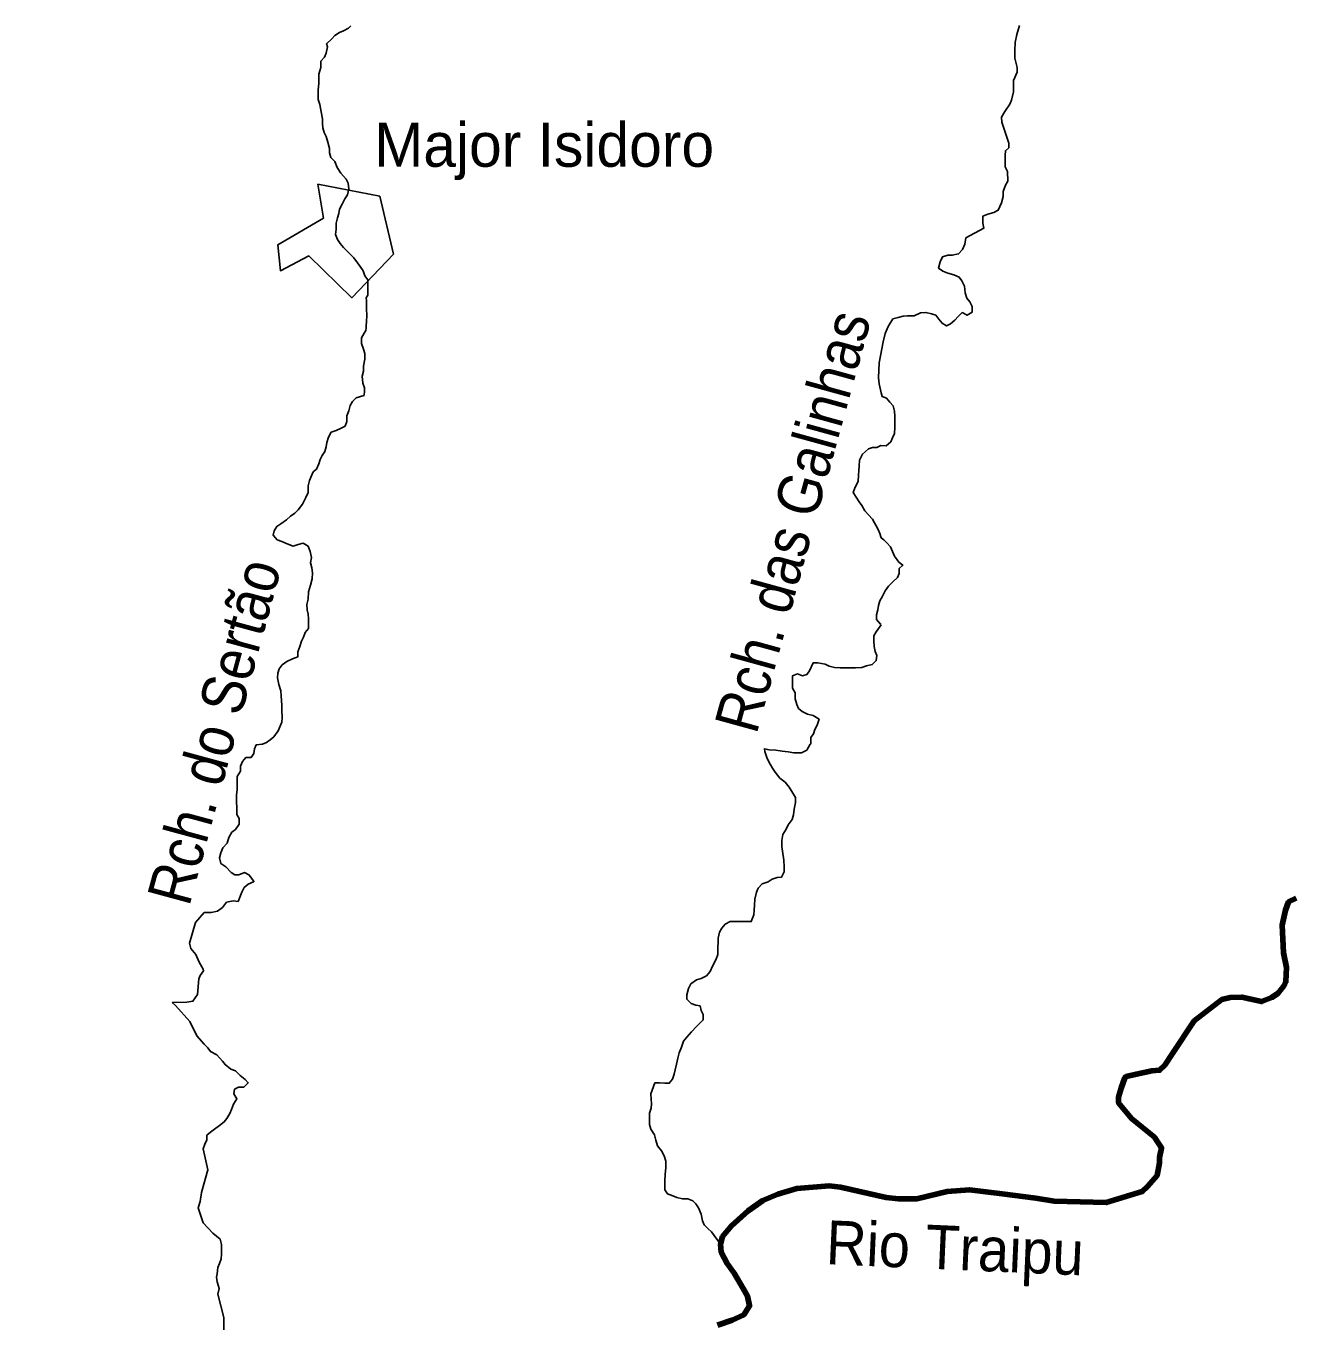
# Model space of a CAD drawing. Extents: x -1643653 to 4543381, y 1624270 to 13878484.
# Drawn here: x 717468 to 731879, y 8933563 to 8948296 of the extents above; entities that cross this region are included whole.
import ezdxf
from ezdxf.enums import TextEntityAlignment as Align

# ---------------------------------------------------------------- set-up
doc = ezdxf.new("R2010")
doc.units = 0
doc.header["$LTSCALE"] = 160
for name, color, linetype, lineweight in [('21', 7, 'Continuous', 25), ('24', 7, 'Continuous', 25), ('53', 7, 'Continuous', 106), ('60', 7, 'Continuous', 13)]:
    doc.layers.add(name, color=color, linetype=linetype, lineweight=lineweight)
doc.layers.add('41', color=7, linetype='Continuous')
doc.layers.add('49', color=7, linetype='Continuous')

msp = doc.modelspace()

# ---------------------------------------------------------------- linework, layer by layer
at = {"layer": '21'}
msp.add_lwpolyline([(720787.1, 8946496.4), (720850.6, 8946110.2), (720334.5, 8945806.5), (720363, 8945511.1), (720684.9, 8945680.2), (721175.9, 8945203.6), (721647.6, 8945700.8), (721491.5, 8946358.8)], close=True, dxfattribs=at)
at = {"layer": '24'}
for points in [[(721162.8, 8948295.4), (721135.4, 8948272.2), (721079.2, 8948242), (721033.3, 8948221.9), (720982.2, 8948186.6), (720946.4, 8948151.1), (720887.8, 8948093.3)], [(728769.3, 8948300.4), (728738.1, 8948198.8), (728717.1, 8948107.2), (728716.5, 8948015.6), (728715.9, 8947929), (728740.6, 8947821.9), (728740.2, 8947771), (728698.8, 8947674.5), (728698.3, 8947603.2), (728698, 8947547.2), (728677, 8947450.6), (728656.3, 8947404.9), (728599.8, 8947323.7), (728563.7, 8947257.7), (728568.4, 8947201.7), (728648.1, 8946961.9), (728647.8, 8946910.9), (728606.8, 8946875.6), (728606.5, 8946824.6), (728605.9, 8946743.2), (728605.6, 8946692.2), (728630.7, 8946641.2), (728635, 8946529.1), (728609.2, 8946483.4), (728583.3, 8946412.3), (728582.9, 8946356.3), (728562.1, 8946285.1), (728525.9, 8946198.8), (728474.8, 8946173.6), (728408.6, 8946153.6), (728352.5, 8946133.6), (728351.9, 8946052.1), (728361.7, 8945996.1), (728366, 8945992.5)], [(720886.8, 8948096.7), (720898.2, 8948057.6), (720882.5, 8947986.4), (720861.8, 8947940.7), (720820.8, 8947895.1), (720820.3, 8947823.8), (720799.5, 8947747.6), (720798.7, 8947640.7), (720793.1, 8947569.4), (720792.8, 8947518.5), (720792.4, 8947457.4), (720812.3, 8947401.2), (720827, 8947319.7), (720841.7, 8947238.1), (720841.4, 8947187.2), (720846.1, 8947136.2), (720861, 8947085.2), (720881, 8947039.2), (720900.9, 8946972.9), (720920.8, 8946901.5), (720920.4, 8946850.6), (720935.3, 8946799.6), (720980.8, 8946753.5), (721005.7, 8946687.1), (721051.1, 8946620.6), (721111.6, 8946554.1), (721131.6, 8946508.1), (721141.3, 8946441.8), (721125.6, 8946375.7), (721094.8, 8946330.1), (721063.9, 8946269.2), (721033, 8946213.3), (721027.5, 8946162.4), (721011.9, 8946111.6), (720996.2, 8946050.6), (720995.8, 8945984.4), (720990.3, 8945923.3), (721010.2, 8945867.2), (721040.4, 8945821.2), (721080.8, 8945775.1), (721116.2, 8945739.2), (721156.6, 8945698.2), (721197, 8945657.3), (721237.2, 8945601), (721267.5, 8945560.1)], [(728361.7, 8945996.1), (728157.5, 8945885.3), (728146.8, 8945814.1), (728121, 8945753.1), (728074.9, 8945702.5), (728003.6, 8945687.6), (727952.7, 8945687.9), (727891.5, 8945667.9), (727865.7, 8945612.1), (727844.9, 8945540.9), (727895.5, 8945505), (727951.3, 8945484.2), (728022.4, 8945463.4), (728083.2, 8945437.6), (728113.5, 8945396.7), (728143.5, 8945335.4), (728148.1, 8945259), (728168, 8945197.7), (728203.3, 8945156.8), (728228.4, 8945105.7), (728228, 8945039.5), (728171.8, 8945004.2), (728116, 8945035.1), (728069.9, 8944989.6), (728034.1, 8944949), (727982.9, 8944908.6), (727937, 8944883.4), (727886.3, 8944914.3), (727851, 8944960.3), (727815.8, 8945006.4), (727765, 8945022), (727704.1, 8945037.6), (727643, 8945032.9), (727571.6, 8944997.7), (727495.3, 8944998.2), (727444.4, 8944993.4), (727388.3, 8944978.4), (727327.2, 8944963.6), (727273, 8944875.7), (727239.5, 8944797.4), (727239.5, 8944797.4), (727217.1, 8944704.3), (727172.4, 8944462.1)], [(721267.5, 8945560.1), (721302.7, 8945508.9), (721322.7, 8945452.8), (721358, 8945406.8), (721357.6, 8945345.6), (721357.2, 8945289.6), (721356.8, 8945233.6), (721336.6, 8945202.4)], [(721333.1, 8944831.8), (721314, 8944802.2), (721283.1, 8944746.3), (721282.7, 8944685.2), (721307.7, 8944618.9), (721322.6, 8944567.9), (721322.1, 8944506.8), (721306.3, 8944425.4), (721305.9, 8944369.4), (721290.3, 8944313.4), (721299.9, 8944231.9), (721319.9, 8944180.8), (721319.5, 8944129.9), (721309.9, 8944083.2)], [(727172.4, 8944462.1), (727164.9, 8944294.4), (727172.4, 8944223.6), (727194.7, 8944123), (727205.5, 8944081.4), (727256.2, 8944060.7), (727291.5, 8944014.6), (727331.9, 8943973.7), (727346.8, 8943912.4), (727351.5, 8943856.4), (727351.1, 8943800.4), (727350.6, 8943729.1), (727345, 8943657.8), (727324.3, 8943612.1), (727303.7, 8943566.4), (727252.5, 8943520.9), (727191.5, 8943521.3), (727145.6, 8943501.2), (727094.7, 8943501.5), (727048.8, 8943486.5), (726982.3, 8943425.8), (726946.2, 8943354.7), (726945.7, 8943288.5), (726940.3, 8943237.7), (726934.9, 8943186.8), (726934.4, 8943115.5), (726898.3, 8943049.5), (726877.6, 8942988.5), (726942.9, 8942881.2), (726973.2, 8942840.2), (727008.3, 8942778.9), (727094.2, 8942686.7), (727159.5, 8942569.2), (727179.5, 8942523.2), (727194.4, 8942472.2)], [(721311.4, 8944090.8), (721222.4, 8944064.3), (721181.5, 8944023.8), (721155.7, 8943978.2), (721140.1, 8943917.2), (721119.3, 8943861.3), (721118.9, 8943795.1), (721098.2, 8943744.3), (721052.2, 8943719.1), (720996.1, 8943694), (720940, 8943673.9), (720909.1, 8943618.1), (720888.3, 8943557.1), (720882.9, 8943506.2), (720867.3, 8943455.4), (720836.5, 8943409.8), (720815.8, 8943364.1), (720800.2, 8943313.2), (720774.3, 8943252.3), (720733.5, 8943222), (720712.8, 8943171.2), (720692.1, 8943125.5), (720676.4, 8943064.5), (720675.9, 8942988.1), (720650.1, 8942932.2), (720613.9, 8942856.1), (720562.6, 8942790.2), (720526.8, 8942754.7), (720475.7, 8942719.4), (720429.6, 8942678.9), (720368.3, 8942633.5), (720322.3, 8942603.2), (720291.4, 8942552.5), (720280.9, 8942501.6), (720326.3, 8942450.4), (720377, 8942429.8), (720437.9, 8942403.9), (720508.9, 8942378), (720565, 8942398), (720621, 8942413), (720676.7, 8942377), (720701.7, 8942315.7), (720716.5, 8942249.4), (720706, 8942188.4), (720720.8, 8942132.3), (720725.5, 8942076.2), (720725, 8942004.9), (720704.2, 8941933.8), (720683.3, 8941857.5), (720677.7, 8941776.1), (720662, 8941715.1), (720666.7, 8941653.9), (720676.5, 8941602.9), (720681.2, 8941552), (720680.8, 8941501.1), (720680.4, 8941440), (720644.5, 8941394.3), (720623.8, 8941343.6), (720603.2, 8941297.8), (720582.4, 8941236.9), (720561.6, 8941175.9), (720561.2, 8941119.9), (720500, 8941094.8), (720433.7, 8941064.6), (720382.6, 8941029.3), (720346.7, 8940983.7), (720331.1, 8940932.9), (720330.7, 8940881.9), (720345.5, 8940805.5), (720365.3, 8940734), (720370, 8940672.9), (720374.7, 8940621.9), (720379.4, 8940565.9), (720379, 8940509.9), (720383.5, 8940428.4), (720378.1, 8940377.5), (720336.7, 8940275.9), (720285.4, 8940210), (720244.5, 8940174.6), (720203.6, 8940144.3), (720157.6, 8940124.2), (720086.4, 8940119.6), (720065.7, 8940073.9), (720060.3, 8940017.9), (720029.4, 8939972.2), (719968.4, 8939972.6), (719932.5, 8939927), (719906.7, 8939876.2), (719906.3, 8939820.2), (719870.3, 8939759.3), (719869.9, 8939703.3), (719869.3, 8939611.7), (719863.7, 8939545.5), (719863.2, 8939464), (719867.9, 8939408), (719867.3, 8939326.5), (719892.4, 8939280.5), (719892, 8939214.3), (719850.8, 8939153.5), (719810, 8939123.2), (719773.9, 8939062.3)], [(727194.4, 8942472.2), (727224.8, 8942451.7), (727260.1, 8942415.8), (727300.5, 8942369.7), (727345.5, 8942262.5), (727395.9, 8942196), (727441.4, 8942160.1), (727443.2, 8942160.1)], [(727441.4, 8942160.1), (727400.5, 8942124.7), (727400.1, 8942068.7), (727379.5, 8942023), (727328.2, 8941972.3), (727277, 8941921.7), (727241.1, 8941871), (727205, 8941800), (727179.2, 8941754.3), (727163.6, 8941703.5), (727158.2, 8941652.6), (727142.6, 8941596.7), (727142.2, 8941545.7), (727187.6, 8941489.4), (727193.7, 8941485.1)], [(727194.1, 8941484.8), (727136.1, 8941403.2), (727110.4, 8941357.5), (727110, 8941301.5), (727114.6, 8941235.3), (727124.4, 8941179.2), (727144.4, 8941133.2), (727139, 8941077.2), (727092.9, 8941031.7), (727026.7, 8941016.8), (726975.7, 8940996.8), (726904.4, 8940992.1), (726853.6, 8940992.4), (726792.5, 8940992.8), (726726.4, 8940993.2), (726665.4, 8940998.7), (726604.5, 8941014.3), (726558.9, 8941035), (726472.5, 8941050.8), (726421.7, 8941051.1), (726380.3, 8940959.7), (726349.5, 8940919.1), (726298.6, 8940904.2), (726242.8, 8940924.9), (726186.7, 8940904.8), (726186.2, 8940833.6), (726185.7, 8940762.3), (726215.9, 8940711.2), (726215.4, 8940639.9), (726235.3, 8940578.6), (726255.3, 8940532.7), (726295.8, 8940496.8), (726356.6, 8940465.9), (726422.6, 8940450.2), (726488.4, 8940409), (726467.6, 8940343), (726441.8, 8940292.2), (726426.2, 8940241.4), (726395.4, 8940200.8), (726394.9, 8940125.5)], [(725866.7, 8940074.6), (725866.7, 8940073.8), (725872.8, 8940040.7), (725897.7, 8939964.2), (725932.8, 8939897.8), (725957.9, 8939851.8), (725988.1, 8939805.8), (726043.6, 8939739.2), (726104.3, 8939693), (726149.7, 8939636.7), (726179.9, 8939585.6), (726220.1, 8939519.2), (726219.7, 8939463.2), (726203.9, 8939386.9), (726198.4, 8939320.7), (726182.8, 8939269.9), (726136.6, 8939209.1), (726115.9, 8939158.2), (726074.8, 8939097.4), (726064.2, 8939031.3), (726063.7, 8938960), (726073.5, 8938909), (726088, 8938807.1), (726092.6, 8938730.6), (726092.2, 8938674.6), (726061.2, 8938613.7), (726010.4, 8938608.9), (725954.3, 8938588.9), (725908.3, 8938558.6), (725842, 8938538.7), (725795.9, 8938488)], [(726388.5, 8940126.2), (726348.7, 8940058.5), (726287.4, 8940028.3), (726201, 8940028.9), (726134.9, 8940039.4), (726068.8, 8940044.9), (725997.7, 8940055.6), (725921.5, 8940061.1), (725866.7, 8940073.8), (725866.7, 8940073.8)], [(719773.9, 8939062.3), (719758.2, 8939001.2), (719707, 8938945.6), (719686.3, 8938889.7), (719670.6, 8938833.7), (719685.4, 8938767.4), (719741.1, 8938731.5), (719801.7, 8938664.9), (719844, 8938640.7), (719890.2, 8938638.6), (719890.2, 8938638.6)], [(720060.8, 8938559.8), (720055.8, 8938559.8), (719994.6, 8938534.7), (719948.5, 8938494.2), (719922.7, 8938443.5), (719881.3, 8938336.8), (719825.4, 8938342.2), (719749, 8938327.4), (719702.8, 8938266.6), (719646.6, 8938226.2), (719575.3, 8938211.3), (719495.9, 8938211.8)], [(719890.2, 8938638.6), (719953.8, 8938664.2), (720004.3, 8938640.4), (720024.2, 8938614.6), (720058.9, 8938563), (720061.4, 8938559.7)], [(725795.9, 8938488), (725775.3, 8938442.3), (725759.4, 8938360.9), (725753.9, 8938294.8), (725748.4, 8938238.8), (725748, 8938182.8), (725717, 8938106.6), (725544.1, 8938107.6), (725478, 8938108), (725421.8, 8938077.8), (725380.8, 8938032.2), (725355.1, 8937986.6), (725339.3, 8937920.5), (725339, 8937869.5), (725338.6, 8937818.6), (725338, 8937732.1), (725317.3, 8937681.2), (725276.1, 8937600), (725250.2, 8937539.1), (725207.8, 8937489.4), (725146.5, 8937460.6), (725092.5, 8937446.2), (725030.6, 8937397.8), (725004.8, 8937347.1), (724984, 8937275.9), (724983.6, 8937225), (725034.1, 8937173.8), (725084.8, 8937158.2), (725135.6, 8937147.7), (725145.5, 8937096.7), (725170.6, 8937050.7), (725170.1, 8936989.6), (725134.3, 8936954.2), (725093.3, 8936913.7), (725037, 8936852.9), (724985.7, 8936792.1), (724944.7, 8936746.5), (724923.9, 8936680.5), (724898, 8936614.4), (724882.3, 8936553.4), (724866.6, 8936487.3), (724850.9, 8936421.2), (724840.4, 8936370.3), (724819.6, 8936314.4), (724783.7, 8936268.8), (724732.8, 8936269.1), (724671.9, 8936274.6), (724621, 8936274.9)], [(719495.9, 8938211.8), (719394.7, 8938096.4), (719328.4, 8937863.4), (719342.1, 8937802.6), (719401.1, 8937732.2), (719437, 8937644.3), (719483.8, 8937567.5), (719487.5, 8937545.9), (719449.3, 8937492.5), (719434.6, 8937455.6), (719420.2, 8937279.4), (719367.4, 8937201.3), (719297.2, 8937190.5), (719130.2, 8937185.6)], [(719130.2, 8937185.6), (719170.7, 8937152.3), (719333.3, 8936971.3), (719410.8, 8936807.6), (719495, 8936711.2)], [(719495, 8936711.2), (719536.3, 8936669.7), (719566.5, 8936628.7), (719637.5, 8936592.7), (719703.1, 8936520.9), (719733.3, 8936480), (719799.1, 8936428.7), (719849.8, 8936408), (719905.4, 8936356.8), (719961, 8936310.6), (719996.4, 8936274.7), (719945.2, 8936224.1), (719884.2, 8936224.5), (719838.2, 8936199.3), (719832.8, 8936148.4), (719868, 8936092.2), (719826.9, 8936031.3), (719806.1, 8935970.3), (719785.5, 8935924.6), (719754.6, 8935868.8), (719723.8, 8935828.3), (719667.5, 8935787.9), (719611.3, 8935747.5), (719565.3, 8935712.1), (719524.3, 8935676.7), (719524, 8935625.8), (719503.3, 8935575), (719482.6, 8935524.2), (719536.9, 8935284.5)], [(724621, 8936274.9), (724573, 8936146.7), (724577.7, 8936085.6), (724582.4, 8936034.6), (724577, 8935983.7), (724561.3, 8935927.8), (724561, 8935876.9), (724560.4, 8935800.5), (724575.3, 8935744.4), (724615.6, 8935683), (724630.4, 8935621.8), (724650.3, 8935555.5), (724695.7, 8935499.2), (724725.8, 8935443), (724745.7, 8935381.8), (724745.2, 8935310.5), (724739.6, 8935229), (724734, 8935157.8), (724733.7, 8935106.9), (724733.3, 8935055.9), (724763.5, 8935009.9), (724824.4, 8934989.2), (724870, 8934968.5), (724936, 8934952.8), (724997.1, 8934952.5), (725052.8, 8934931.8), (725088.2, 8934895.9), (725118.4, 8934849.9), (725148.4, 8934778.4), (725163.2, 8934701.9), (725183.2, 8934656), (725223.6, 8934615), (725264, 8934579.1), (725368.5, 8934436.4)], [(719536.9, 8935284.5), (719464.5, 8935025.4), (719447.8, 8934924.5), (719426.1, 8934849.8), (719483, 8934679.3)], [(719483, 8934679.3), (719595.3, 8934563.2), (719635.8, 8934527.3), (719676.2, 8934496.5), (719691.1, 8934435.3), (719690.7, 8934384.4), (719690.3, 8934323.2), (719690, 8934272.3), (719669.2, 8934217.6), (719651.2, 8934174.2), (719643, 8934099.5), (719634.9, 8934064), (719642.2, 8934009.8), (719665.6, 8933932.1), (719651.2, 8933868.8), (719718.1, 8933604.6), (719714.8, 8933203.5)]]:
    msp.add_lwpolyline(points, dxfattribs=at)
at = {"layer": '24', "lineweight": 53}
for points in [[(731915.4, 8938374.6), (731827.8, 8938330.7), (731791.3, 8938235.8), (731754.8, 8938067.7), (731769.4, 8937753.5), (731805.9, 8937585.5), (731798.6, 8937424.7), (731776.7, 8937380.9), (731711.1, 8937293.2), (731638.1, 8937242.1), (731521.3, 8937198.2), (731382.6, 8937227.4), (731295, 8937249.4), (731163.7, 8937242.1), (731068.8, 8937220.1), (730754.9, 8936979), (730506.8, 8936606.4), (730419.2, 8936474.9), (730360.8, 8936416.4), (730273.2, 8936409.1), (730098.1, 8936372.6), (729981.3, 8936343.4), (729966.7, 8936328.8), (729922.9, 8936211.9), (729893.7, 8936109.6), (729893.7, 8936043.8), (730039.7, 8935868.4), (730302.4, 8935656.6), (730346.2, 8935590.8), (730382.7, 8935532.3), (730360.8, 8935422.8), (730360.8, 8935364.3), (730331.6, 8935218.2), (730222.1, 8935094), (730163.7, 8935035.5), (729755, 8934911.3), (729163.8, 8934925.9), (728952.2, 8934962.4), (728571.5, 8935009.7), (728200.4, 8935057.4), (727944.9, 8935035.5), (727601.9, 8934955.1), (727390.2, 8934955.1), (727251.6, 8934969.8), (726733.4, 8935086.7)], [(726733.4, 8935086.7), (726602, 8935101.3), (726237.1, 8935072), (726018.1, 8935006.3), (725850.2, 8934933.2), (725682.3, 8934816.3), (725492.6, 8934648.3), (725390.4, 8934524.1), (725368.5, 8934436.4), (725375.8, 8934348.7), (725441.5, 8934217.2), (725521.8, 8934107.6), (725624, 8933932.2), (725675.1, 8933844.6), (725697, 8933734.9), (725631.3, 8933632.7), (725499.9, 8933574.2), (725332, 8933515.8)]]:
    msp.add_lwpolyline(points, dxfattribs=at)
at = {"layer": '24'}
msp.add_spline([(721338.8, 8945205.7), (721343, 8945051.6), (721343, 8944957), (721332, 8944830.1)], degree=3, dxfattribs=at)
at = {"layer": '53'}
for points in [[(731915.4, 8938374.6), (731827.8, 8938330.7), (731791.3, 8938235.8), (731754.8, 8938067.7), (731769.4, 8937753.5), (731805.9, 8937585.5), (731798.6, 8937424.7), (731776.7, 8937380.9), (731711.1, 8937293.2), (731638.1, 8937242.1), (731521.3, 8937198.2), (731382.6, 8937227.4), (731295, 8937249.4), (731163.7, 8937242.1), (731068.8, 8937220.1), (730754.9, 8936979), (730506.8, 8936606.4), (730419.2, 8936474.9), (730360.8, 8936416.4), (730273.2, 8936409.1), (730098.1, 8936372.6), (729981.3, 8936343.4), (729966.7, 8936328.8), (729922.9, 8936211.9), (729893.7, 8936109.6), (729893.7, 8936043.8), (730039.7, 8935868.4), (730302.4, 8935656.6), (730346.2, 8935590.8), (730382.7, 8935532.3), (730360.8, 8935422.8), (730360.8, 8935364.3), (730331.6, 8935218.2), (730222.1, 8935094), (730163.7, 8935035.5), (729755, 8934911.3), (729163.8, 8934925.9), (728952.2, 8934962.4), (728571.5, 8935009.7), (728200.4, 8935057.4), (727944.9, 8935035.5), (727601.9, 8934955.1), (727390.2, 8934955.1), (727251.6, 8934969.8), (726733.4, 8935086.7)], [(731915.4, 8938374.6), (731827.8, 8938330.7), (731791.3, 8938235.8), (731754.8, 8938067.7), (731769.4, 8937753.5), (731805.9, 8937585.5), (731798.6, 8937424.7), (731776.7, 8937380.9), (731711.1, 8937293.2), (731638.1, 8937242.1), (731521.3, 8937198.2), (731382.6, 8937227.4), (731295, 8937249.4), (731163.7, 8937242.1), (731068.8, 8937220.1), (730754.9, 8936979), (730506.8, 8936606.4), (730419.2, 8936474.9), (730360.8, 8936416.4), (730273.2, 8936409.1), (730098.1, 8936372.6), (729981.3, 8936343.4), (729966.7, 8936328.8), (729922.9, 8936211.9), (729893.7, 8936109.6), (729893.7, 8936043.8), (730039.7, 8935868.4), (730302.4, 8935656.6), (730346.2, 8935590.8), (730382.7, 8935532.3), (730360.8, 8935422.8), (730360.8, 8935364.3), (730331.6, 8935218.2), (730222.1, 8935094), (730163.7, 8935035.5), (729755, 8934911.3), (729163.8, 8934925.9), (728952.2, 8934962.4), (728571.5, 8935009.7), (728200.4, 8935057.4), (727944.9, 8935035.5), (727601.9, 8934955.1), (727390.2, 8934955.1), (727251.6, 8934969.8), (726733.4, 8935086.7)], [(731915.4, 8938374.6), (731827.8, 8938330.7), (731791.3, 8938235.8), (731754.8, 8938067.7), (731769.4, 8937753.5), (731805.9, 8937585.5), (731798.6, 8937424.7), (731776.7, 8937380.9), (731711.1, 8937293.2), (731638.1, 8937242.1), (731521.3, 8937198.2), (731382.6, 8937227.4), (731295, 8937249.4), (731163.7, 8937242.1), (731068.8, 8937220.1), (730754.9, 8936979), (730506.8, 8936606.4), (730419.2, 8936474.9), (730360.8, 8936416.4), (730273.2, 8936409.1), (730098.1, 8936372.6), (729981.3, 8936343.4), (729966.7, 8936328.8), (729922.9, 8936211.9), (729893.7, 8936109.6), (729893.7, 8936043.8), (730039.7, 8935868.4), (730302.4, 8935656.6), (730346.2, 8935590.8), (730382.7, 8935532.3), (730360.8, 8935422.8), (730360.8, 8935364.3), (730331.6, 8935218.2), (730222.1, 8935094), (730163.7, 8935035.5), (729755, 8934911.3), (729163.8, 8934925.9), (728952.2, 8934962.4), (728571.5, 8935009.7), (728200.4, 8935057.4), (727944.9, 8935035.5), (727601.9, 8934955.1), (727390.2, 8934955.1), (727251.6, 8934969.8), (726733.4, 8935086.7)], [(726733.4, 8935086.7), (726602, 8935101.3), (726237.1, 8935072), (726018.1, 8935006.3), (725850.2, 8934933.2), (725682.3, 8934816.3), (725492.6, 8934648.3), (725390.4, 8934524.1), (725368.5, 8934436.4), (725375.8, 8934348.7), (725441.5, 8934217.2), (725521.8, 8934107.6), (725624, 8933932.2), (725675.1, 8933844.6), (725697, 8933734.9), (725631.3, 8933632.7), (725499.9, 8933574.2), (725332, 8933515.8)], [(726733.4, 8935086.7), (726602, 8935101.3), (726237.1, 8935072), (726018.1, 8935006.3), (725850.2, 8934933.2), (725682.3, 8934816.3), (725492.6, 8934648.3), (725390.4, 8934524.1), (725368.5, 8934436.4), (725375.8, 8934348.7), (725441.5, 8934217.2), (725521.8, 8934107.6), (725624, 8933932.2), (725675.1, 8933844.6), (725697, 8933734.9), (725631.3, 8933632.7), (725499.9, 8933574.2), (725332, 8933515.8)], [(726733.4, 8935086.7), (726602, 8935101.3), (726237.1, 8935072), (726018.1, 8935006.3), (725850.2, 8934933.2), (725682.3, 8934816.3), (725492.6, 8934648.3), (725390.4, 8934524.1), (725368.5, 8934436.4), (725375.8, 8934348.7), (725441.5, 8934217.2), (725521.8, 8934107.6), (725624, 8933932.2), (725675.1, 8933844.6), (725697, 8933734.9), (725631.3, 8933632.7), (725499.9, 8933574.2), (725332, 8933515.8)]]:
    msp.add_lwpolyline(points, dxfattribs=at)
at = {"layer": '60', "lineweight": 25}
msp.add_spline([(814781, 9009175.5), (814787.2, 9009173.4), (814796.9, 9009173.4), (814799.4, 9009172.4), (814805.1, 9009174.5), (814805.6, 9009176.5), (814811.7, 9009179.5), (814811.7, 9009179.5), (814801.5, 9009181), (814790.7, 9009181.5), (814784.1, 9009183.1), (814777.4, 9009185.1), (814778.4, 9009175.5)], degree=3, dxfattribs=at)

# ---------------------------------------------------------------- texts
at = {"layer": '41'}
msp.add_text('Major Isidoro', height=500, dxfattribs=at).set_placement((721429.9, 8946693.7))
at = {"layer": '49'}
for s, rotation, width, p in [('Rch. das Galinhas', 74.592, 0.9, (726429.3, 8942595.9)), ('Rch. do Sertão', 74.808, 0.9, (719849.9, 8940205)), ('Rio Traipu', 357.482, 0.95, (728023.7, 8934146.6))]:
    msp.add_text(s, height=500, rotation=rotation, dxfattribs=dict(at, width=width)).set_placement(p, align=Align.CENTER)

doc.saveas('drawing.dxf')
